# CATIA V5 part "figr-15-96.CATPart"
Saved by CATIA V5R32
Part number: Part1
Bounding box of the stored display mesh (mm): x -31.325 to 48, y -66.072 to 47.73, z 0 to 2
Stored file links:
  D:\PROJECTS\Project 2022\CATIA V5 6R 2022\Resources\Part Files\c15_catia_v5_6r2022_prt\figr-15-96.CATPart
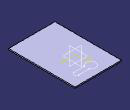
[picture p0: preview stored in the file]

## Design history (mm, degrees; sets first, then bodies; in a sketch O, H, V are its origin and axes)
SheetMetalParameters1: Thickness 2, BendRadius 4, KFactor 0.400515 {= log(min(100,max(20*SheetMetalParameters1.BendRadius,SheetMetalParameters1.Thickness)/SheetMetalParameters1.Thickness))/log(100)/2}, ReliefRadialLength 1, ReliefAxialLength 2, MinimumBendRadius 0
Body1 (main body)
  Sketch1 on xy-plane, origin (0, 0, 0), H (1, 0, 0), V (0, 1, 0)
    line L1 (-31.3255, 47.7299) -> (48, 47.7299)
    line L2 (48, 47.7299) -> (48, -66.0715)
    line L3 (48, -66.0715) -> (-31.3255, -66.0715)
    line L4 (-31.3255, -66.0715) -> (-31.3255, 47.7299)
    horizontal: L1 H, L3 H
    vertical: L2 V, L4 V
  Wall1: Thickness 2, Profile Sketch1, OffsetValue 0
  Sketch2 on face of Wall1, origin (0, 0, 2), H (1, 0, 0), V (0, 1, 0)
    construction line L1 (2.2258, 29) -> (27.2258, 29)
    point P1 (2.2258, 29)
    point P2 (27.2258, 29)
    line L2 (27.2258, 25) -> (9.154, 25)
    line L3 (9.154, 33) -> (27.2258, 33)
    arc A1 centre (2.2258, 29) radius 8 from (9.154, 25) to (9.154, 33) cw
    arc A2 centre (27.2258, 29) radius 4 from (27.2258, 33) to (27.2258, 25) cw
    radius A1 = 8
    radius A2 = 4
    distance P2 P1 = 25
    horizontal: L1 H
    tangency: A2 L2, A2 L3
    parallelism: L2 L3, L2 L1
